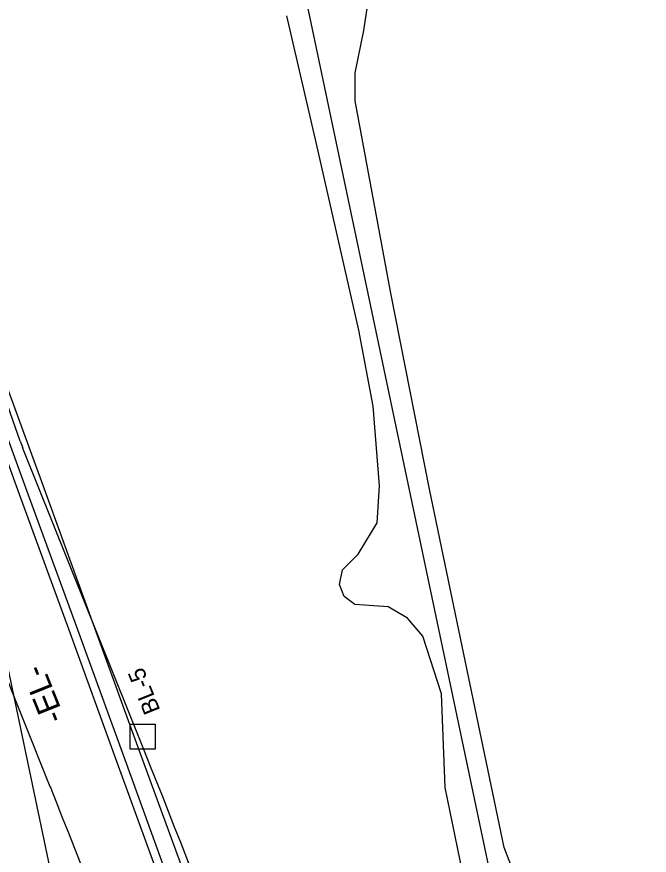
# Model space of a CAD drawing. Extents: x 1611576 to 1617186, y 899279 to 905462.
# Drawn here: x 1616172.8 to 1616361.3, y 904028.8 to 904278.6 of the extents above; entities that cross this region are included whole.
import ezdxf

# ---------------------------------------------------------------- set-up
doc = ezdxf.new("R2010")
doc.units = 0
for name, color, linetype in [('CTL Secondary Horizontal and Vertical CELL', 7, 'Continuous'), ('CTL Secondary Horizontal and Vertical Text', 7, 'Continuous'), ('Exist Horizontal Alignment', 7, 'Continuous'), ('Exist Horizontal Alignment Direction Label', 7, 'Continuous'), ('Exist Right of Way Line', 7, 'Continuous'), ('Exist Roads Curbs', 7, 'Continuous'), ('Exist Roads EOP', 7, 'Continuous'), ('Exist Roads EOP Other', 7, 'Continuous'), ('Exist Vegetation Hedge Row', 7, 'Continuous'), ('Exist Vegetation Woods Line', 7, 'Continuous')]:
    doc.layers.add(name, color=color, linetype=linetype)

# ---------------------------------------------------------------- blocks, each defined once
blk = doc.blocks.new('CTL SECONDARY HORIZONTAL AND VERTICAL')
at = {"layer": 'CTL Secondary Horizontal and Vertical CELL'}
blk.add_line((0, 0), (0, 0), dxfattribs=at)
blk.add_lwpolyline([(-0.1043, 0.0004), (0.0005, 0.1052), (0.1055, 0.0002), (0.0007, -0.1047)], close=True, dxfattribs=at)

msp = doc.modelspace()

# ---------------------------------------------------------------- linework, layer by layer
at = {"layer": 'Exist Horizontal Alignment'}
msp.add_line((1616182.78, 904049.14), (1616146.69, 904139.07), dxfattribs=at)
msp.add_arc((1612992.37, 902768.76), 3437.75, 19.23333, 21.86667, dxfattribs=at)
at = {"layer": 'Exist Right of Way Line'}
for p, q in [((1616010.65, 905462.23), (1616993.32, 900797.76)), ((1615887.44, 905426.15), (1616864.55, 900788.06)), ((1616173.83, 904152.11), (1616108.23, 904338.4)), ((1616210.62, 904060.32), (1616174.53, 904150.24))]:
    msp.add_line(p, q, dxfattribs=at)
for centre, radius, start, end in [((1616217.59, 904167.52), 46.39, 199.4, 201.8667), ((1612992.37, 902768.76), 3467.75, 19.23333, 21.86667)]:
    msp.add_arc(centre, radius, start, end, dxfattribs=at)
at = {"layer": 'Exist Roads Curbs'}
msp.add_lwpolyline([(1616117.86, 904294.32), (1616132.6, 904254.66), (1616147.03, 904215.59), (1616161.55, 904176.09), (1616175.82, 904137.25), (1616190.47, 904097.09), (1616204.98, 904057.33), (1616219.73, 904016.73), (1616233.88, 903976.63), (1616247.93, 903936.53), (1616261.75, 903896.6), (1616275.82, 903856.12), (1616289.5, 903816.57), (1616303.58, 903775.98), (1616318, 903734.48)], dxfattribs=at)
at = {"layer": 'Exist Roads EOP'}
for points in [[(1616115.61, 904293.45), (1616130.22, 904253.88), (1616144.71, 904214.78), (1616159.36, 904175.17), (1616173.54, 904136.33), (1616188.19, 904096.22), (1616202.56, 904056.51), (1616217.36, 904015.9), (1616231.52, 903975.89), (1616245.62, 903935.7), (1616259.38, 903895.73), (1616273.35, 903855.36), (1616287.12, 903815.79), (1616301.21, 903775.08), (1616315.66, 903733.58)], [(1616115.61, 904293.45), (1616130.22, 904253.88), (1616144.71, 904214.78), (1616159.36, 904175.17), (1616173.54, 904136.33), (1616188.19, 904096.22), (1616202.56, 904056.51), (1616217.36, 904015.9), (1616231.52, 903975.89), (1616245.62, 903935.7), (1616259.38, 903895.73), (1616273.35, 903855.36), (1616287.12, 903815.79)]]:
    msp.add_lwpolyline(points, dxfattribs=at)
at = {"layer": 'Exist Roads EOP Other'}
msp.add_lwpolyline([(1616122.43, 904296.46), (1616137.34, 904256.3), (1616151.63, 904217.58), (1616166.45, 904177.4), (1616180.52, 904139.04), (1616195.16, 904098.73), (1616209.58, 904059.11), (1616224.45, 904018.46), (1616238.58, 903978.47), (1616252.68, 903938.24), (1616266.45, 903898.41), (1616280.47, 903857.78), (1616294.14, 903818.38), (1616308.3, 903777.63), (1616322.66, 903736.35)], dxfattribs=at)
at = {"layer": 'Exist Vegetation Hedge Row'}
msp.add_lwpolyline([(1616358.61, 903855.18), (1616347.94, 903857.23), (1616338.59, 903879.82), (1616325.43, 903934.2), (1616310.92, 903998.19), (1616300.46, 904048.92), (1616299.41, 904076.85), (1616293.79, 904094.09), (1616289.23, 904099.45), (1616283.51, 904102.81), (1616273.57, 904103.44), (1616270.33, 904105.91), (1616268.99, 904109.41), (1616269.89, 904113.78), (1616274.57, 904118.52), (1616280.14, 904127.79), (1616280.93, 904138.82), (1616278.97, 904162.54), (1616274.72, 904185.17), (1616262.08, 904240.76), (1616253.29, 904278.87)], dxfattribs=at)
at = {"layer": 'Exist Vegetation Woods Line'}
msp.add_lwpolyline([(1616365.59, 903820.6), (1616353.15, 903884.59), (1616347.73, 903925.27), (1616338.73, 903963.54), (1616335.36, 903990.43), (1616333.66, 903998.74), (1616328.38, 904009.6), (1616321.8, 904021.23), (1616318.01, 904031.04), (1616304.54, 904095.81), (1616295.76, 904137.81), (1616284.29, 904196.22), (1616273.61, 904253.55), (1616273.63, 904261.89), (1616276.22, 904274.47), (1616277.23, 904281.08), (1616276.85, 904288.34)], dxfattribs=at)

# ---------------------------------------------------------------- block references
at = {"layer": 'CTL Secondary Horizontal and Vertical CELL', "xscale": 50, "yscale": 49.99999999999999, "rotation": 44.99999999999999}
msp.add_blockref('CTL SECONDARY HORIZONTAL AND VERTICAL', (1616210.29, 904064.07), dxfattribs=at)
msp.add_blockref('CTL SECONDARY HORIZONTAL AND VERTICAL', (1616210.29, 904064.07), dxfattribs=at)

# ---------------------------------------------------------------- texts
at = {"layer": 'CTL Secondary Horizontal and Vertical Text'}
msp.add_text('BL-5', height=5, rotation=111.8667, dxfattribs=at).set_placement((1616215.62, 904072))
at = {"layer": 'Exist Horizontal Alignment Direction Label'}
msp.add_text('-EL-', height=7, rotation=111.8667, dxfattribs=at).set_placement((1616187.18, 904069.67))

doc.saveas('drawing.dxf')
